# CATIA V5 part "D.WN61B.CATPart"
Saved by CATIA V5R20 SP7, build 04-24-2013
Part number: D.WN61B
Material "Nessuno"
Bounding box of the stored display mesh (mm): x 0 to 150.807, y -135.185 to 0, z -91.151 to 75.737
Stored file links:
  C:\Users\designer2\Desktop\Ottobre 2022\25-10-2022\04\Yori Evo 48V\D.WN61B.CATPart
  C:\Users\designer2\Desktop\Ottobre 2022\25-10-2022\04\Yori Evo 48V\D.WN61B_AllCATPart.CATPart
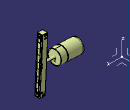
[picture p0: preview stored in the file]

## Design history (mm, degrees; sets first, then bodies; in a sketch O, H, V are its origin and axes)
AxisSystem1: origin (0, 0, 0), X (1, 0, 0), Y (0, 1, 0), Z (0, 0, 1)
Set1
  DatumSurface1
Body1 (main body), material "Nessuno"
